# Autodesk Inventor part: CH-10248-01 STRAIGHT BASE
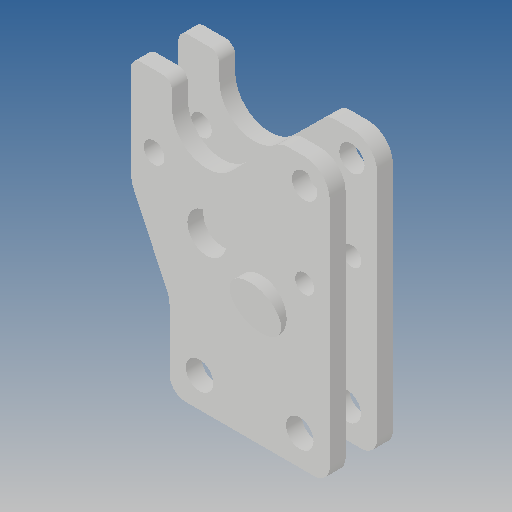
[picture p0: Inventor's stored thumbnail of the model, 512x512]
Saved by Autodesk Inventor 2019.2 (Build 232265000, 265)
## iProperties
Created: 2012-09
Part Number: CH-10248-01 STRAIGHT BASE
Material: Ogólny
Document SubType Name: Modeling
Designer: CADENGINEERING4
Density: 1 g/cm^3
Appearance: Domyślna
Author: CADENGINEERING4
Revision Number: ÈÎºÎ
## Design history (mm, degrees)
feature "À­Éì6[1]"
feature "À­Éì6[2]"
node "Bryła1"
node "Bryła2"
